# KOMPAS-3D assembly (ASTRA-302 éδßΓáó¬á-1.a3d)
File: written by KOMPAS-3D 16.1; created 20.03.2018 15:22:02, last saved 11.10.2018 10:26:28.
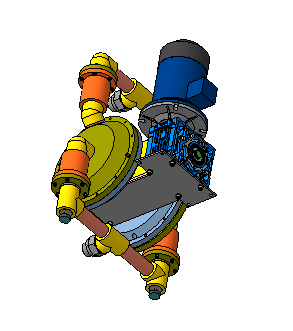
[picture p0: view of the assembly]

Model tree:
1. Эскиз:2
2. Операция выдавливания:1  (labels: C:\Program Files\ASCON\KOMPAS-3D V16\Sys\bo_atr.lat)
     Расстояние 1 = 6; Расстояние = -0.5; Расстояние = -0.5; Расстояние = 1; Расстояние = 15

Expressions: A2-70; М6 x 50 - A2-70
Referenced files in Z:\Мембранные насосы\Мембранный электропривод\А302-00.00.000 - ASTRA-302 (МЭ200)\3Д\: А302-00.15.001 - Мембрана.a3d, А302-00.10.000 - Рабочая камера.a3d, А302-00.05.002 - Ловитель.m3d, А302-00.05.001 - Основание.m3d, Выставка - Основание.m3d, А302-00.35.000 - Фланец.a3d, А302-00.20.002 - Эксцентрик.m3d, А302-00.20.004 - Вал.m3d, А302-00.20.003 - Ползун.m3d
Referenced files in C:\Program Files\ASCON\KOMPAS-3D V16\Libs\PartLib\DATA\vault\Methods\Kompas\3D\: PLib_Washer_1_712.m3d, PLib_Washer_2_712.m3d, PLib_Screw_DIN_7984_1500.m3d, PLib_Check_spring_rings_GOST_13942_911.m3d, PLib_Key_prismatic_712.m3d
Referenced files in Z:\1 ПКИ 3D\Полипропиленовые фитинги, трубы\: Колено 90гр 40 FV PPR ф. FV PLAST.m3d, Тройник 40 FV PPR ф. FV PLAST.m3d, Переходник с пластмассовой резьбой наружной 40х1 1_4 FV PPR ф.FV Plast.m3d
Referenced files in Z:\1 ПКИ 3D\Полипропиленовые фитинги, трубы\Трубы\: Труба 40 PN10 S=3,7 FV PPR ф. FV PLAST.m3d
Referenced files in C:\Program Files\ASCON\KOMPAS-3D V16\Libs\PartLib\DATA\VAULT\Methods\kompas\3d\: PLib_Washer_2_712.m3d, PLib_Bolt_1_900.m3d, PLib_Nut_OST92_900.m3d
Referenced files in D:\3Д модели\Крепеж\: Гайка шестигранная самостопорящаяся с фланцем DIN 6927-M6 - A2-70.m3d
Referenced files in Z:\1 ПКИ 3D\1 Крепеж стандартный\Подшипник\: Подшипник радиально-упорный 80х40х18 7208 BEP SKF.m3d, Подшипниковый узел UCF207 ISB EcoLine.m3d, Подшипник 52х25х15 62052RSH SKF.m3d
Referenced files in Z:\Мембранные насосы\Мембранный электропривод\А302-00.00.000 - ASTRA-302 (МЭ200)\3Д ПВХ\Отработка\: Упор.m3d, Упор-1.m3d, Фиксатор.m3d
Referenced files in Z:\1 ПКИ 3D\Редуктора NMRW\Редукторы\: Червячный мотор-редуктор NMRV063 АИР80.a3d
Referenced files in Z:\1 ПКИ 3D\Крепеж\: Опора резьбовая М6х60 черн. арт. 32М6-60ЧН.m3d
Referenced files: graphic.tdp
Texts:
  (-) А302-00.15.000 Мембрана (1)
  (+) А302-00.15.000 Мембрана (2)
  Сталь 20 ГОСТ 1050-2013
  Шайба C 12.04.019 ГОСТ 6958-78
  Крепежное изделие ГОСТ
  (-) Шайба C 12.04.019 ГОСТ 6958-78 (1)
  (-) Шайба C 12.04.019 ГОСТ 6958-78 (2)
  (ф) А302-00.10.000 Рабочая камера (1)
  (ф) А302-00.10.000 Рабочая камера (2)
  Колено 90@1~ @2~40 FV PPR ф. "FV PLAST"
  (-) Колено 90гр 40 FV PPR ф. FV PLAST
  Тройник @2~40 FV PPR ф. "FV PLAST"
  (-) Тройник 40 FV PPR ф. FV PLAST (1)
  (-) Тройник 40 FV PPR ф. FV PLAST (2)
  (-) Тройник 40 FV PPR ф. FV PLAST (3)
  (-) Тройник 40 FV PPR ф. FV PLAST (4)
  Труба 40 PN10 S=3,7 FV PPR ф. FV PLAST
  (-) Труба ф40х3,7 (PN10) FV PPR ф. FV PLAST (1)
  (-) Труба ф40х3,7 (PN10) FV PPR ф. FV PLAST (2)
  Переходник с пластмассовой резьбой
  наружной 40х1 1/4" FV PPR
  ф. "FV PLAST"
  Переходник с пластмассовой резьбой  / наружной 40х1 1/4" FV PPR  / ф. "FV PLAST"
  (-) Переходник с пластмассовой резьбой наружной 40х1 1/4" FV PPR ф."FV Plast" (1)
  (-) Труба ф40х3,7 (PN10) FV PPR ф. FV PLAST (3)
  (-) Переходник с пластмассовой резьбой наружной 40х1 1/4" FV PPR ф."FV Plast" (2)
  (-) Переходник с пластмассовой резьбой наружной 40х1 1/4" FV PPR ф."FV Plast" (3)
  Сталь 12Х18Н10Т ГОСТ 5632-72
  Шайба C.6.21 ГОСТ 11371-78
  (-) Шайба C.6.21 ГОСТ 11371-78 (1)
  Сталь 30Х13 ГОСТ 5632-72
  Шайба 6 30Х13 019 ГОСТ 6402-70
  (-) Шайба 6 30Х13 019 ГОСТ 6402-70 (1)
  Винт с цилиндрической головкой и шестигранным углублением под ключ ГОСТ Р ИСО 4762 - М6 x 50 - A2-70
  Винт с цилиндрической головкой
  и шестигранным углублением под ключ
  ГОСТ Р ИСО  4762-М6 x 50-A2-70
  Винт с цилиндрической головкой и шестигранным углублением под ключ
  (-) Винт с цилиндрической головкой и шестигранным углублением под ключ ГОСТ Р ИСО 4762 - М6 x 50 - A2-70 (1)
  Гайка шестигранная самостопорящаяся
  с фланцем DIN 6927-M6-A2-70
  (-) Гайка шестигранная самостопорящаяся с фланцем DIN 6927-M6 - A2-70 (1)
  (-) Гайка шестигранная самостопорящаяся с фланцем DIN 6927-M6 - A2-70 (2)
  (-) Шайба C.6.21 ГОСТ 11371-78 (2)
  (-) Шайба 6 30Х13 019 ГОСТ 6402-70 (2)
  Винт с цилиндрической головкой и шестигранным углублением под ключ ГОСТ Р ИСО  4762-М6 x 50-A2-70
  (-) Винт с цилиндрической головкой и шестигранным углублением под ключ ГОСТ Р ИСО 4762 - М6 x 50 - A2-70 (2)
  (-) А302-00.05.002 Ловитель (1)
  (ф) А302-00.05.001 Основание (1)
  (-) А302-00.05.002 Ловитель (2)
  (ф) А302-00.05.001 Основание (2)
  Шайба C.8.21 ГОСТ 11371-78
  (-) Шайба C.8.21 ГОСТ 11371-78
  Шайба C 8.04.019 ГОСТ 6958-78
  (-) Шайба C 8.04.019 ГОСТ 6958-78
  Шайба 8 30Х13 019 ГОСТ 6402-70
  (-) Шайба 8 30Х13 019 ГОСТ 6402-70
  Болт М8-6gx30.58.019 ГОСТ 7805-70
  hole1
  hole2
  (-) Болт М8-6gx30.58.019 ГОСТ 7805-70
  Гайка М8-6H.5.019 ГОСТ 5915-70
  bcut1
  hcut1
  cut1
  (-) Гайка М8-6H.5.019 ГОСТ 5915-70
  Подшипник радиально-упорный 80х40х18 7208 BEP SKF
  (-) Подшипник радиально-упорный 80х40х18 7208 BEP SKF
  Подшипниковый узел UCF207 ISB EcoLine
  (-) Подшипниковый узел UCF207 ISB EcoLine
  (-) А302-01.05.012 Фиксатор
  (-) А302-01.05.014 Упор
  NMRV063 N P(кВт) V5
  P(мощн./дв.), i(передат. отн.) см. заказ
  Мотор-редуктор / NMRV063 N P(кВт) V5 / P(мощн./дв.), i(передат. отн.) см. заказ
  Двигатель1400 об/минN=1400/i
  (ф) Червячный мотор-редуктор NMRV063 АИР80
  (ф) А302-00.20.001 Основание
  (ф) А302-00.35.000 Фланец
  (-) А302-00.20.002 Эксцентрик
  Сталь 65Г ГОСТ 14959-79
  Кольцо A25.65Г ГОСТ 13942-86
  Isp3
  (-) Кольцо A25.65Г ГОСТ 13942-86
  Подшипник 52х25х15 62052RSH SKF
  (-) Подшипник 52х25х15 62052RSH SKF
  (-) А302-00.20.004 Вал
  (-) А302-00.20.003 Ползун
  Шайба C.5.04.019 ГОСТ 11371-78
  (-) Шайба C.5.04.019 ГОСТ 11371-78
  Болт М5-6gx35.58.019 ГОСТ 7805-70
  (-) Болт М5-6gx35.58.019 ГОСТ 7805-70
  Шайба 5 30Х13 019 ГОСТ 6402-70
  (-) Шайба 5 30Х13 019 ГОСТ 6402-70
  Гайка М5-6H.5.019 ГОСТ 5915-70
  (-) Гайка М5-6H.5.019 ГОСТ 5915-70
  Шайба C.8.04.019 ГОСТ 11371-78
  (-) Шайба C.8.04.019 ГОСТ 11371-78
  Винт с цилиндрической головкой и шестигранным углублением под ключ ГОСТ Р ИСО 4762 - М8 x 20 - 6.8 - A9J
  (-) Винт с цилиндрической головкой и шестигранным углублением под ключ ГОСТ Р ИСО 4762 - М8 x 20 - 6.8 - A9J
  Винт с цилиндрической головкой и шестигранным углублением под ключ ГОСТ Р ИСО 4762 - М8 x 35 - 6.8 - A9J
  (-) Винт с цилиндрической головкой и шестигранным углублением под ключ ГОСТ Р ИСО 4762 - М8 x 35 - 6.8 - A9J
  Шпонка 8x7x90 ГОСТ 23360-78
  skr2
  skr1
  Шпонка 8 x 7 x 90 ГОСТ 23360-78
  (-) Шпонка 8x7x90 ГОСТ 23360-78
  (-) Тройник 40 FV PPR ф. FV PLAST (5)
  Опора резьбовая М6х60 черная
  арт. 32М6-60ЧН
  Опора резьбовая М6х60 черная  / арт. 32М6-60ЧН
  (-) Опора резьбовая М6х60 черн. арт. 32М6-60ЧН (1)
  (-) Опора резьбовая М6х60 черн. арт. 32М6-60ЧН (2)
  ASTRA-302 Выставка
  ГОСТ 6958-78
  ГОСТ 11371-78
  ГОСТ 6402-70
  ГОСТ Р ИСО 4762-2012
  ГОСТ 7805-70
  М8-6gx30.58.019
  ГОСТ 5915-70
  ГОСТ 13942-86
  М5-6gx35.58.019
  ГОСТ 23360-78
